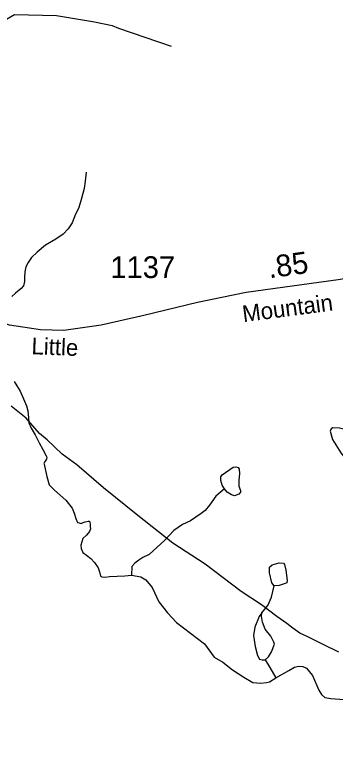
# Model space of a CAD drawing. Extents: x 2056842 to 2160602, y 826753 to 1016856.
# Drawn here: x 2077140 to 2078980, y 892991 to 897187 of the extents above; entities that cross this region are included whole.
import ezdxf

# ---------------------------------------------------------------- set-up
doc = ezdxf.new("R2010")
doc.units = 0
for name, color, linetype in [('Exist Hydrographic Creek Single Shore', 7, 'Continuous'), ('Exist Hydrographic Misc Water Feature', 7, 'Continuous'), ('Exist Road Non-System Type 51', 7, 'Continuous'), ('Exist Road Secondary Mileage Hundredths English Label', 7, 'Continuous'), ('Exist Road Secondary Type 51 Attributed', 7, 'Continuous'), ('Exist Road Secondary Type 51 Label', 7, 'Continuous'), ('Exist Road Secondary Type 51 Number Label', 7, 'Continuous'), ('Exist Utilities Electrical Transmission Line', 7, 'Continuous')]:
    doc.layers.add(name, color=color, linetype=linetype)

msp = doc.modelspace()

# ---------------------------------------------------------------- linework, layer by layer
at = {"layer": 'Exist Hydrographic Creek Single Shore'}
for points in [[(2077551, 896282.6), (2077544.9, 896230.8), (2077539.1, 896188.6), (2077531.5, 896160.5), (2077519.4, 896116.6), (2077505.7, 896074.4), (2077489.7, 896040.3), (2077470, 895990.6), (2077446, 895956.4), (2077418.1, 895926.2), (2077376.1, 895898.1), (2077316, 895862.1), (2077268.6, 895821.8), (2077236.5, 895791.8), (2077216.4, 895763.6), (2077204.7, 895739.4), (2077198.9, 895709.4), (2077196.9, 895677.7), (2077196.9, 895653.8), (2077191.1, 895629.5), (2077177, 895613.4), (2077145.4, 895587.3), (2077123.5, 895567.4)], [(2077136.8, 895079.3), (2077152.8, 895055.3), (2077170.8, 895025.5), (2077191.1, 894981.4), (2077207.1, 894939.6), (2077215.1, 894911.6), (2077219.4, 894871.6), (2077221.7, 894843.6), (2077235.4, 894811.5), (2077257.6, 894773.7), (2077279.7, 894727.7), (2077301.9, 894689.8), (2077320.1, 894653.8), (2077323.8, 894645.9), (2077322.4, 894634), (2077314.4, 894621.8), (2077308, 894609.7), (2077308.2, 894606), (2077316.2, 894570), (2077324.4, 894534.3), (2077338.4, 894485.9), (2077368.7, 894456.2), (2077400.7, 894428.2), (2077432.7, 894398.1), (2077469.2, 894352.4), (2077481.1, 894324.6), (2077491.1, 894292.7), (2077501, 894270.5), (2077509.2, 894268.4), (2077521.3, 894264.6), (2077533.4, 894270.5), (2077545.1, 894274.8), (2077561.1, 894278.9), (2077569, 894278.9), (2077573.1, 894262.8), (2077573.1, 894247), (2077575.4, 894234.9), (2077569.3, 894218.7), (2077551.4, 894198.7), (2077531.5, 894178.6), (2077519.6, 894140.7), (2077521.5, 894120.9), (2077531.9, 894098.6), (2077551.6, 894082.7), (2077576, 894064.7), (2077598, 894041.1), (2077618.1, 894010.9), (2077625.8, 893987), (2077632, 893962.9), (2077640.2, 893958.8), (2077659.9, 893957.1), (2077684.1, 893961.2), (2077772.1, 893963.6), (2077810.5, 893969)], [(2077810.5, 893969), (2077862.9, 893959), (2077891.6, 893941.5), (2077929, 893897.8), (2077967.7, 893814.2), (2078016.4, 893751.8), (2078068.8, 893696.9), (2078229.7, 893573.3), (2078269.5, 893518.9), (2078285.3, 893497), (2078334.5, 893468.5), (2078389.3, 893424.8), (2078454.1, 893381.8), (2078505.8, 893351.2), (2078552, 893347.4), (2078585.7, 893351.2), (2078603.1, 893356.1), (2078639.3, 893378.6)], [(2078639.3, 893378.6), (2078712.9, 893421.1), (2078746.6, 893439.8), (2078767.8, 893446), (2078792.8, 893443.5), (2078815.2, 893433.5), (2078848.9, 893392.3), (2078885.9, 893306.9), (2078899.8, 893282.8), (2078920.3, 893265.2), (2078954.2, 893259.3), (2079030, 893253.4), (2079062.4, 893243.7), (2079098.3, 893213.8), (2079132.1, 893151.2), (2079140.8, 893115), (2079147, 893070.1), (2079148.3, 892962.7)]]:
    msp.add_lwpolyline(points, dxfattribs=at)
at = {"layer": 'Exist Hydrographic Misc Water Feature'}
for points in [[(2079094.6, 894705.4), (2079105.9, 894757.8), (2079112.1, 894785.3), (2079108.4, 894795.3), (2079098.4, 894800.2), (2079064.7, 894797.7), (2079004.8, 894812.7), (2078964.9, 894814), (2078956.2, 894809), (2078951.2, 894795.3), (2078963.7, 894746.6), (2079011.1, 894670.4), (2079059.7, 894610.5), (2079072.2, 894608), (2079080.9, 894618), (2079084.7, 894669.2), (2079094.6, 894705.4)], [(2078344.4, 894463.3), (2078329.7, 894485), (2078322.2, 894511.2), (2078322.2, 894533.6), (2078331, 894543.6), (2078393.3, 894587.3), (2078409.5, 894589.8), (2078423.3, 894586.1), (2078428.3, 894577.3), (2078429.5, 894552.4), (2078425.8, 894511.2), (2078425.8, 894478.7), (2078435.7, 894455), (2078435.7, 894443.8), (2078427, 894432.5), (2078400.8, 894423.8), (2078383.4, 894428.8), (2078359.7, 894445), (2078344.4, 894463.3)], [(2078344.4, 894463.3), (2078294.5, 894420.8), (2078258.4, 894370.9), (2078232.2, 894339.7), (2078209.7, 894322.2), (2078148.6, 894281), (2078103.7, 894258.6), (2078053.8, 894224.9), (2078001.4, 894169.9), (2077911.7, 894087.7), (2077876, 894069.9), (2077852.9, 894053.9), (2077829.2, 894037.6), (2077813, 894017.7), (2077810.5, 893969)], [(2078628.1, 893907.1), (2078615.6, 893923.3), (2078603.1, 893982), (2078603.1, 894014.4), (2078616.9, 894026.9), (2078656.8, 894039.4), (2078681.7, 894036.9), (2078689.2, 894029.4), (2078696.7, 893996.9), (2078704.2, 893938.3), (2078701.7, 893924.6), (2078693, 893919.6), (2078658, 893909.6), (2078628.1, 893907.1)], [(2078558.2, 893752.3), (2078591.9, 893793.5), (2078614.4, 893840.9), (2078628.1, 893907.1)], [(2078558.2, 893752.3), (2078543.3, 893729.8), (2078518.3, 893668.7), (2078509.6, 893622.5), (2078520.8, 893558.8), (2078533.3, 893506.4), (2078544.5, 893486.5), (2078560.7, 893481.5), (2078578.2, 893482.2)], [(2078578.2, 893482.2), (2078596.9, 893498.9), (2078613.1, 893527.6), (2078630.6, 893571.3), (2078626.9, 893582.6), (2078609.4, 893617.5), (2078578.2, 893657.4), (2078562, 893698.6), (2078557, 893733.6), (2078558.2, 893752.3)], [(2078578.2, 893482.2), (2078604.4, 893437.3), (2078639.3, 893378.6)]]:
    msp.add_lwpolyline(points, dxfattribs=at)
at = {"layer": 'Exist Road Non-System Type 51'}
msp.add_lwpolyline([(2076519.6, 896842.7), (2076567.1, 896903.5), (2076605.8, 897007.9), (2076659.4, 897079.4), (2076760.7, 897106.3), (2076897.8, 897082.4), (2077022.9, 897121.2), (2077139.1, 897186.8), (2077380.4, 897180.8), (2077597.9, 897145), (2077699.2, 897124.2), (2077734.9, 897109.2), (2078038.8, 897004.9)], dxfattribs=at)
at = {"layer": 'Exist Road Secondary Type 51 Attributed'}
msp.add_lwpolyline([(2080868, 895982.2), (2080810.5, 895985.8), (2080747.7, 895980.4), (2080452.2, 895923.7), (2080015.6, 895844.7), (2079421.9, 895734.1), (2078996.2, 895664), (2078469, 895591.2), (2078188.7, 895533.7), (2077881.5, 895460), (2077635.4, 895404.2), (2077422.6, 895372.8), (2077287.8, 895376.4), (2077110, 895403.3), (2076919.6, 895468), (2076691.4, 895570.5), (2076509.9, 895655.9)], dxfattribs=at)
at = {"layer": 'Exist Utilities Electrical Transmission Line'}
msp.add_lwpolyline([(2079000.3, 893525.8), (2078910.2, 893569.5), (2078822.1, 893613.3), (2078775.9, 893635), (2078735.9, 893662.9), (2078701.9, 893690.8), (2078643.7, 893730.6), (2078555.5, 893798.4), (2078439.3, 893874), (2078232.7, 894031.3), (2078048.4, 894152.7), (2077846, 894310.1), (2077649.5, 894469.4), (2077497, 894601), (2077412.9, 894662.7), (2077326.8, 894744.5), (2077282.6, 894782.2), (2077206.4, 894870), (2077120.2, 894937.8)], dxfattribs=at)

# ---------------------------------------------------------------- texts
at = {"layer": 'Exist Road Secondary Mileage Hundredths English Label'}
msp.add_text('.85', height=125, rotation=7.8622, dxfattribs=at).set_placement((2078601.2, 895672.5))
at = {"layer": 'Exist Road Secondary Type 51 Label'}
for s, rotation, p in [('Mountain', 7.4901, (2078452.5, 895420.6)), ('Little', 357.768, (2077234.9, 895237))]:
    msp.add_text(s, height=95, rotation=rotation, dxfattribs=at).set_placement(p)
at = {"layer": 'Exist Road Secondary Type 51 Number Label'}
msp.add_text('1137', height=125, dxfattribs=at).set_placement((2077688.9, 895674.1))

doc.saveas('drawing.dxf')
